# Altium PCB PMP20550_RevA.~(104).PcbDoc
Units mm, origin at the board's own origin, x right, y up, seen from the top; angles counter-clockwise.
Board outline 49.95 x 50.01 mm, 4 copper layers (Top Layer, POWER, GNDS, Bottom Layer), stack 2.028 mm thick; 55 components, 23 nets, 128 pads, 85 vias.
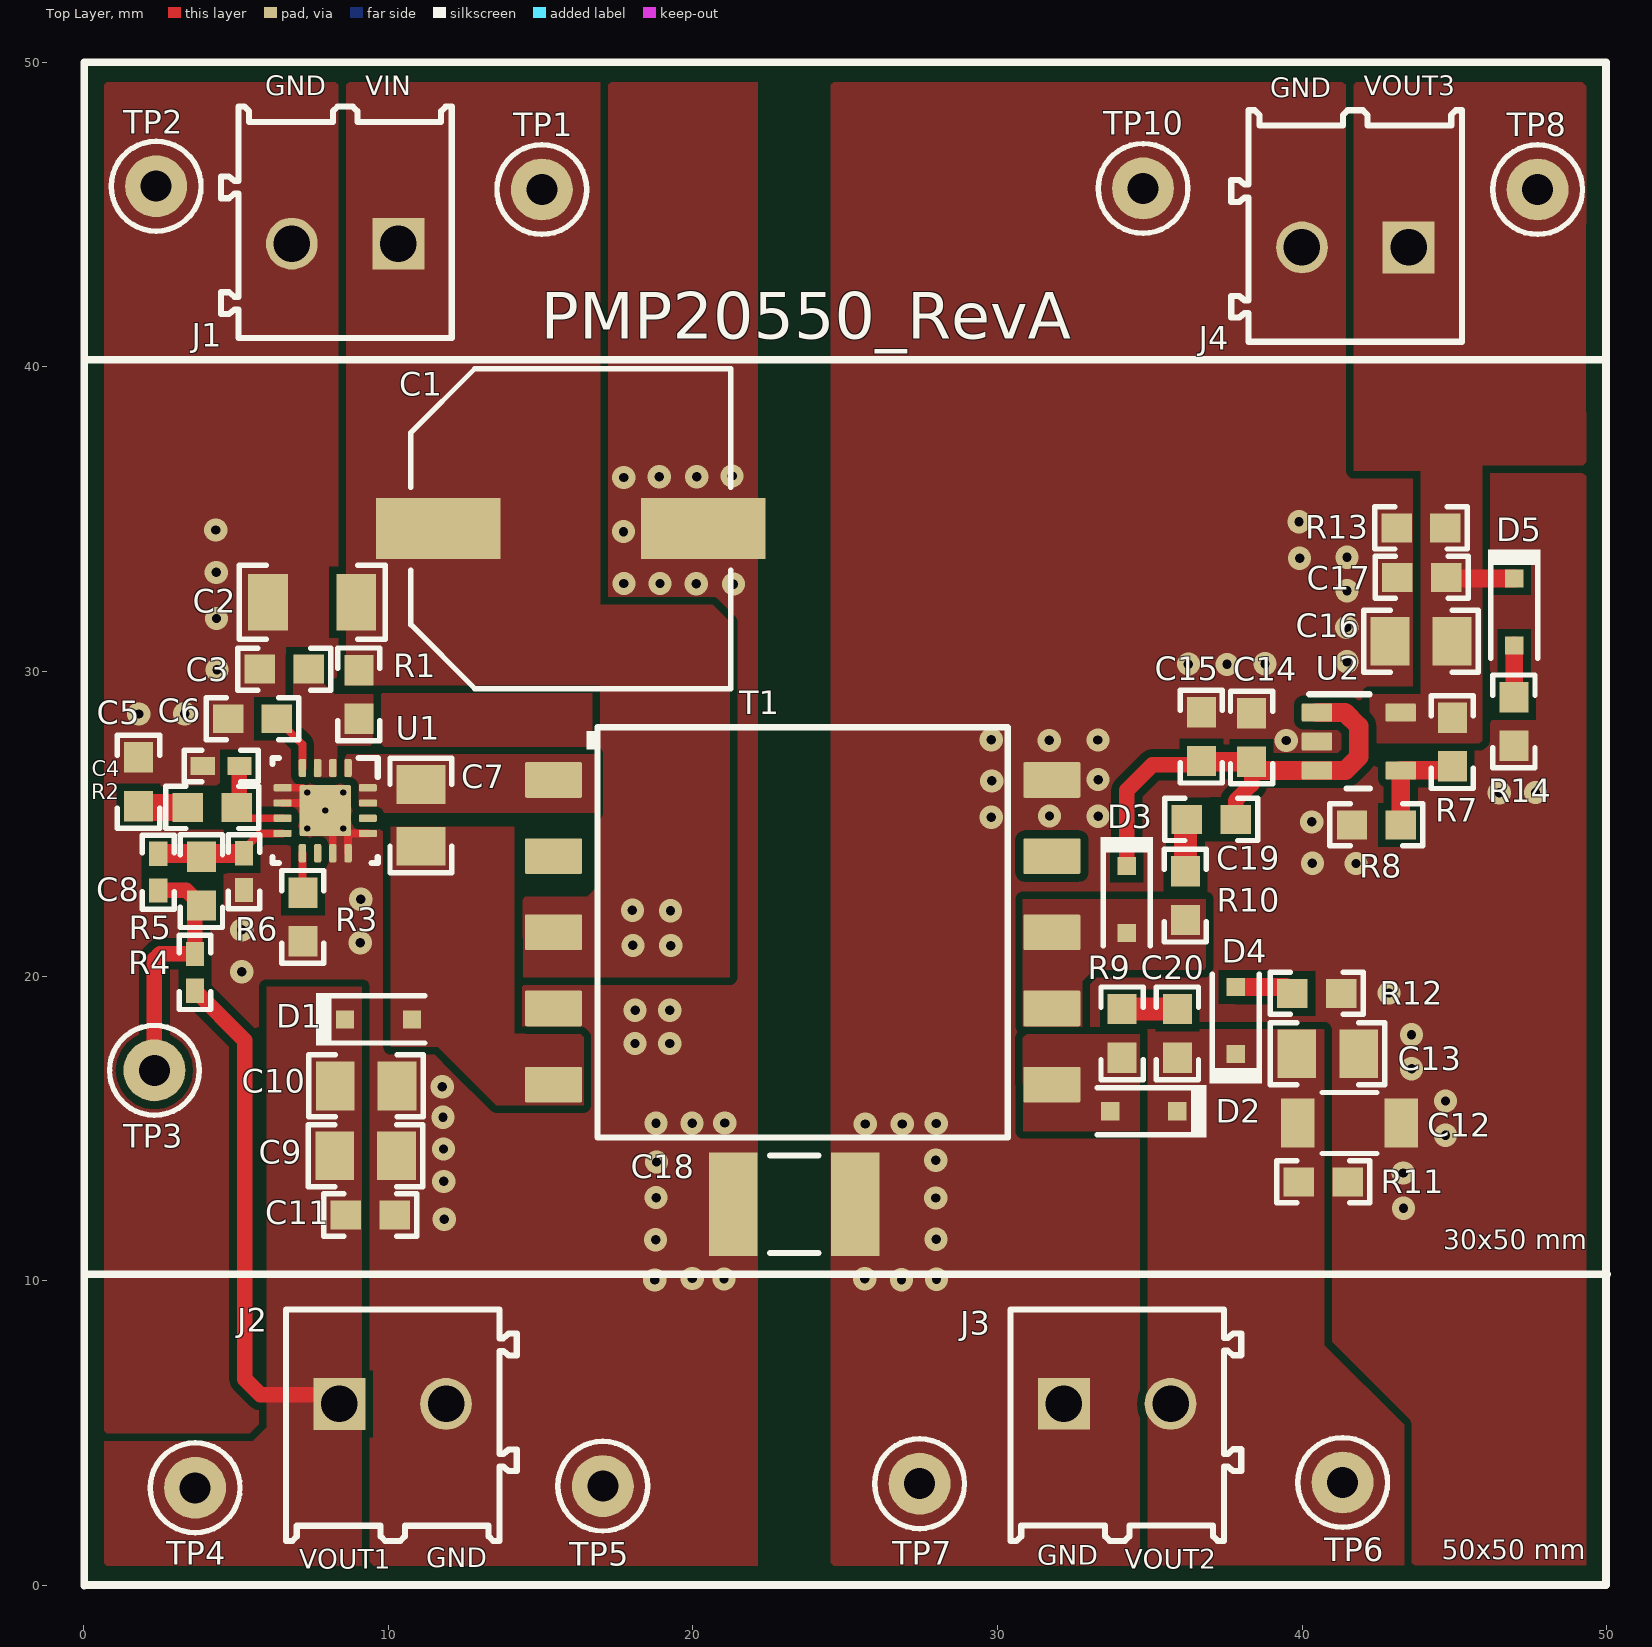
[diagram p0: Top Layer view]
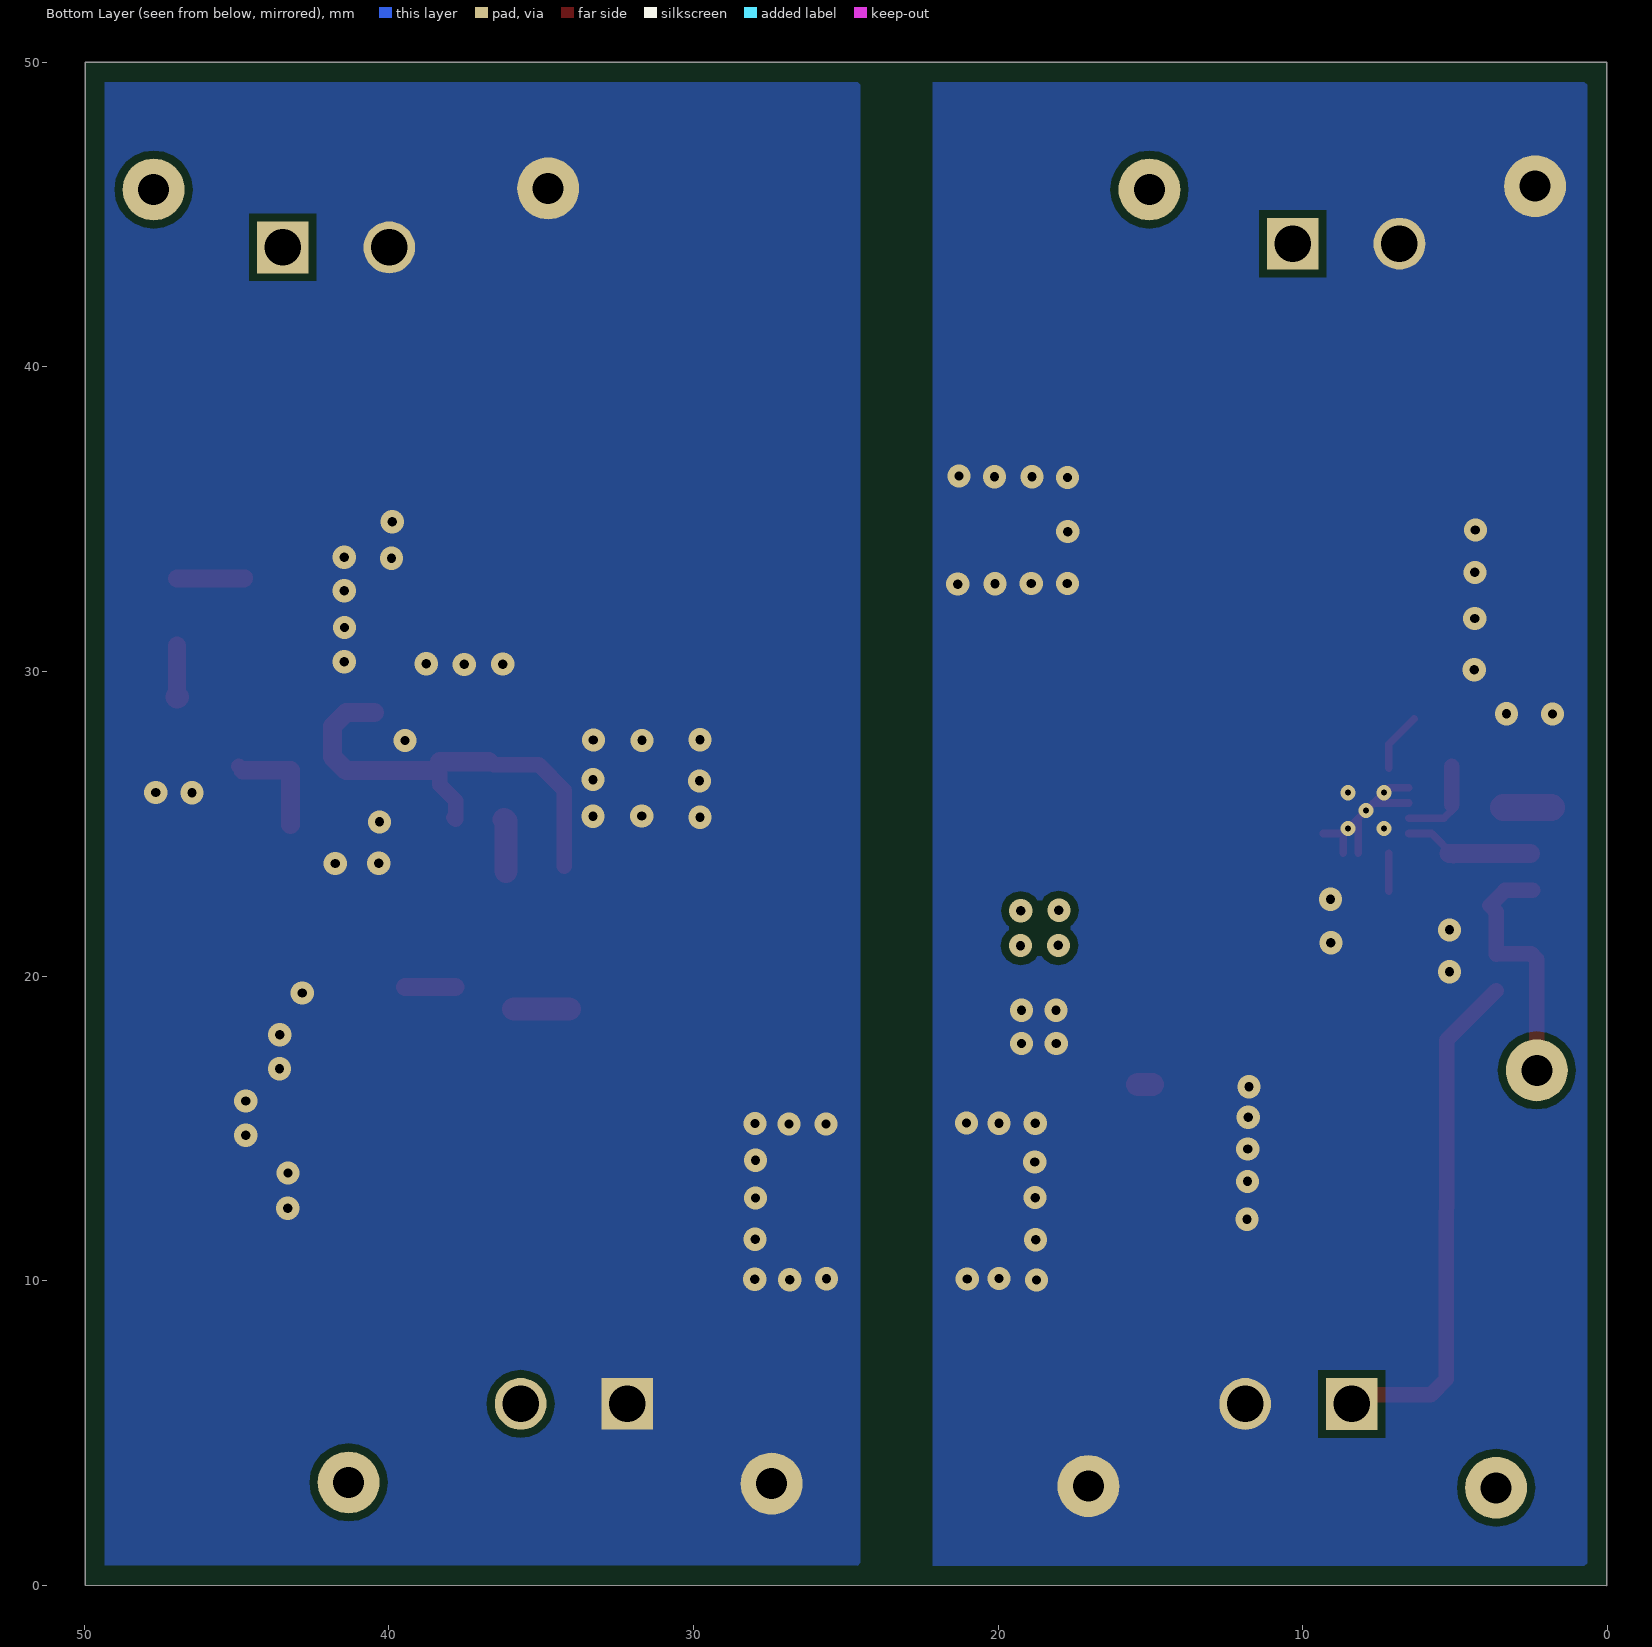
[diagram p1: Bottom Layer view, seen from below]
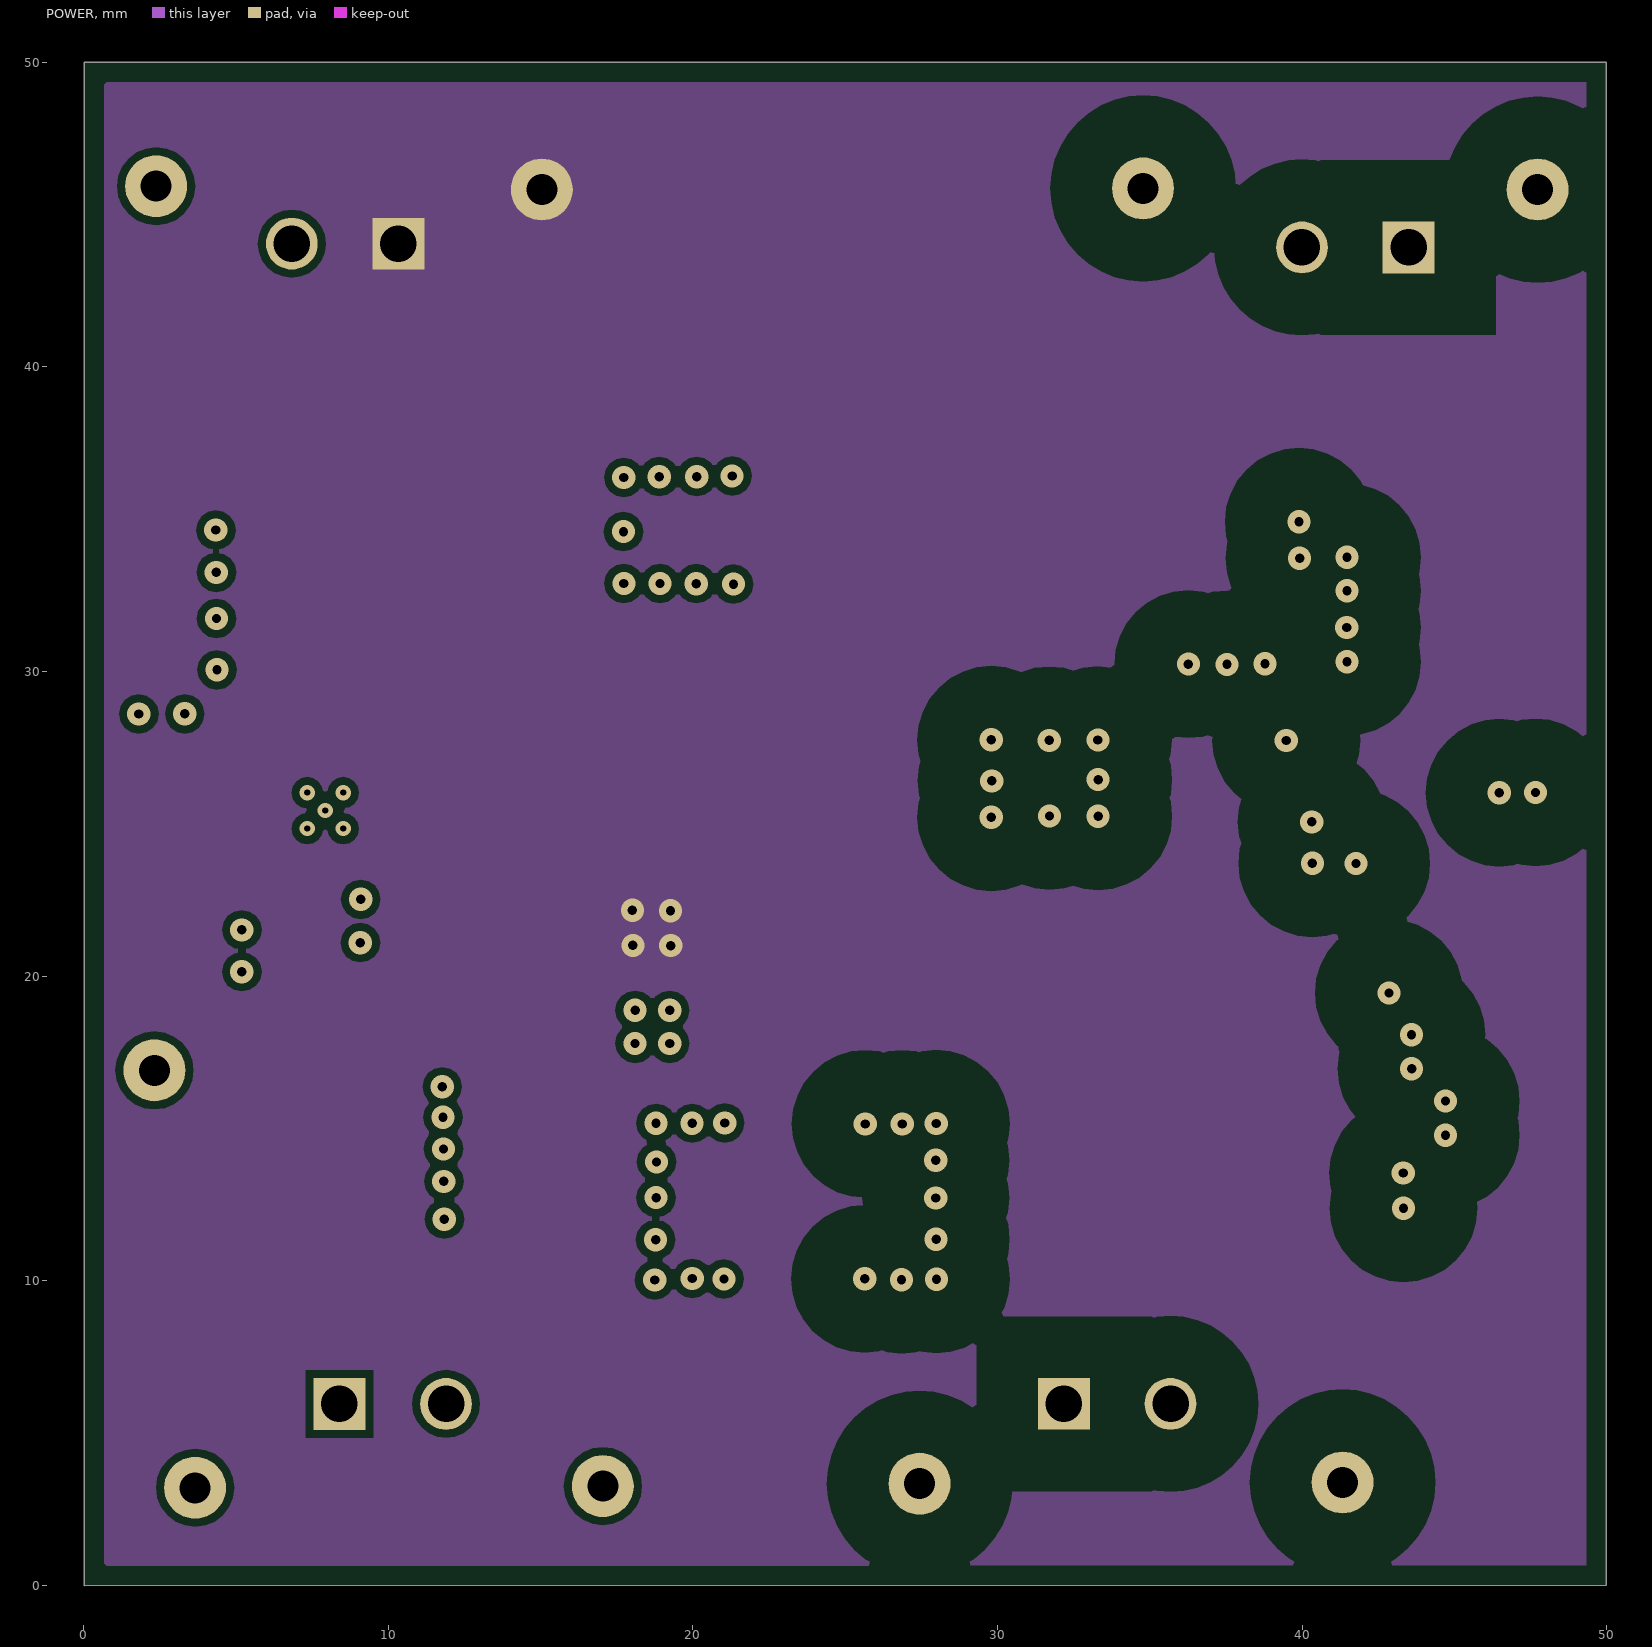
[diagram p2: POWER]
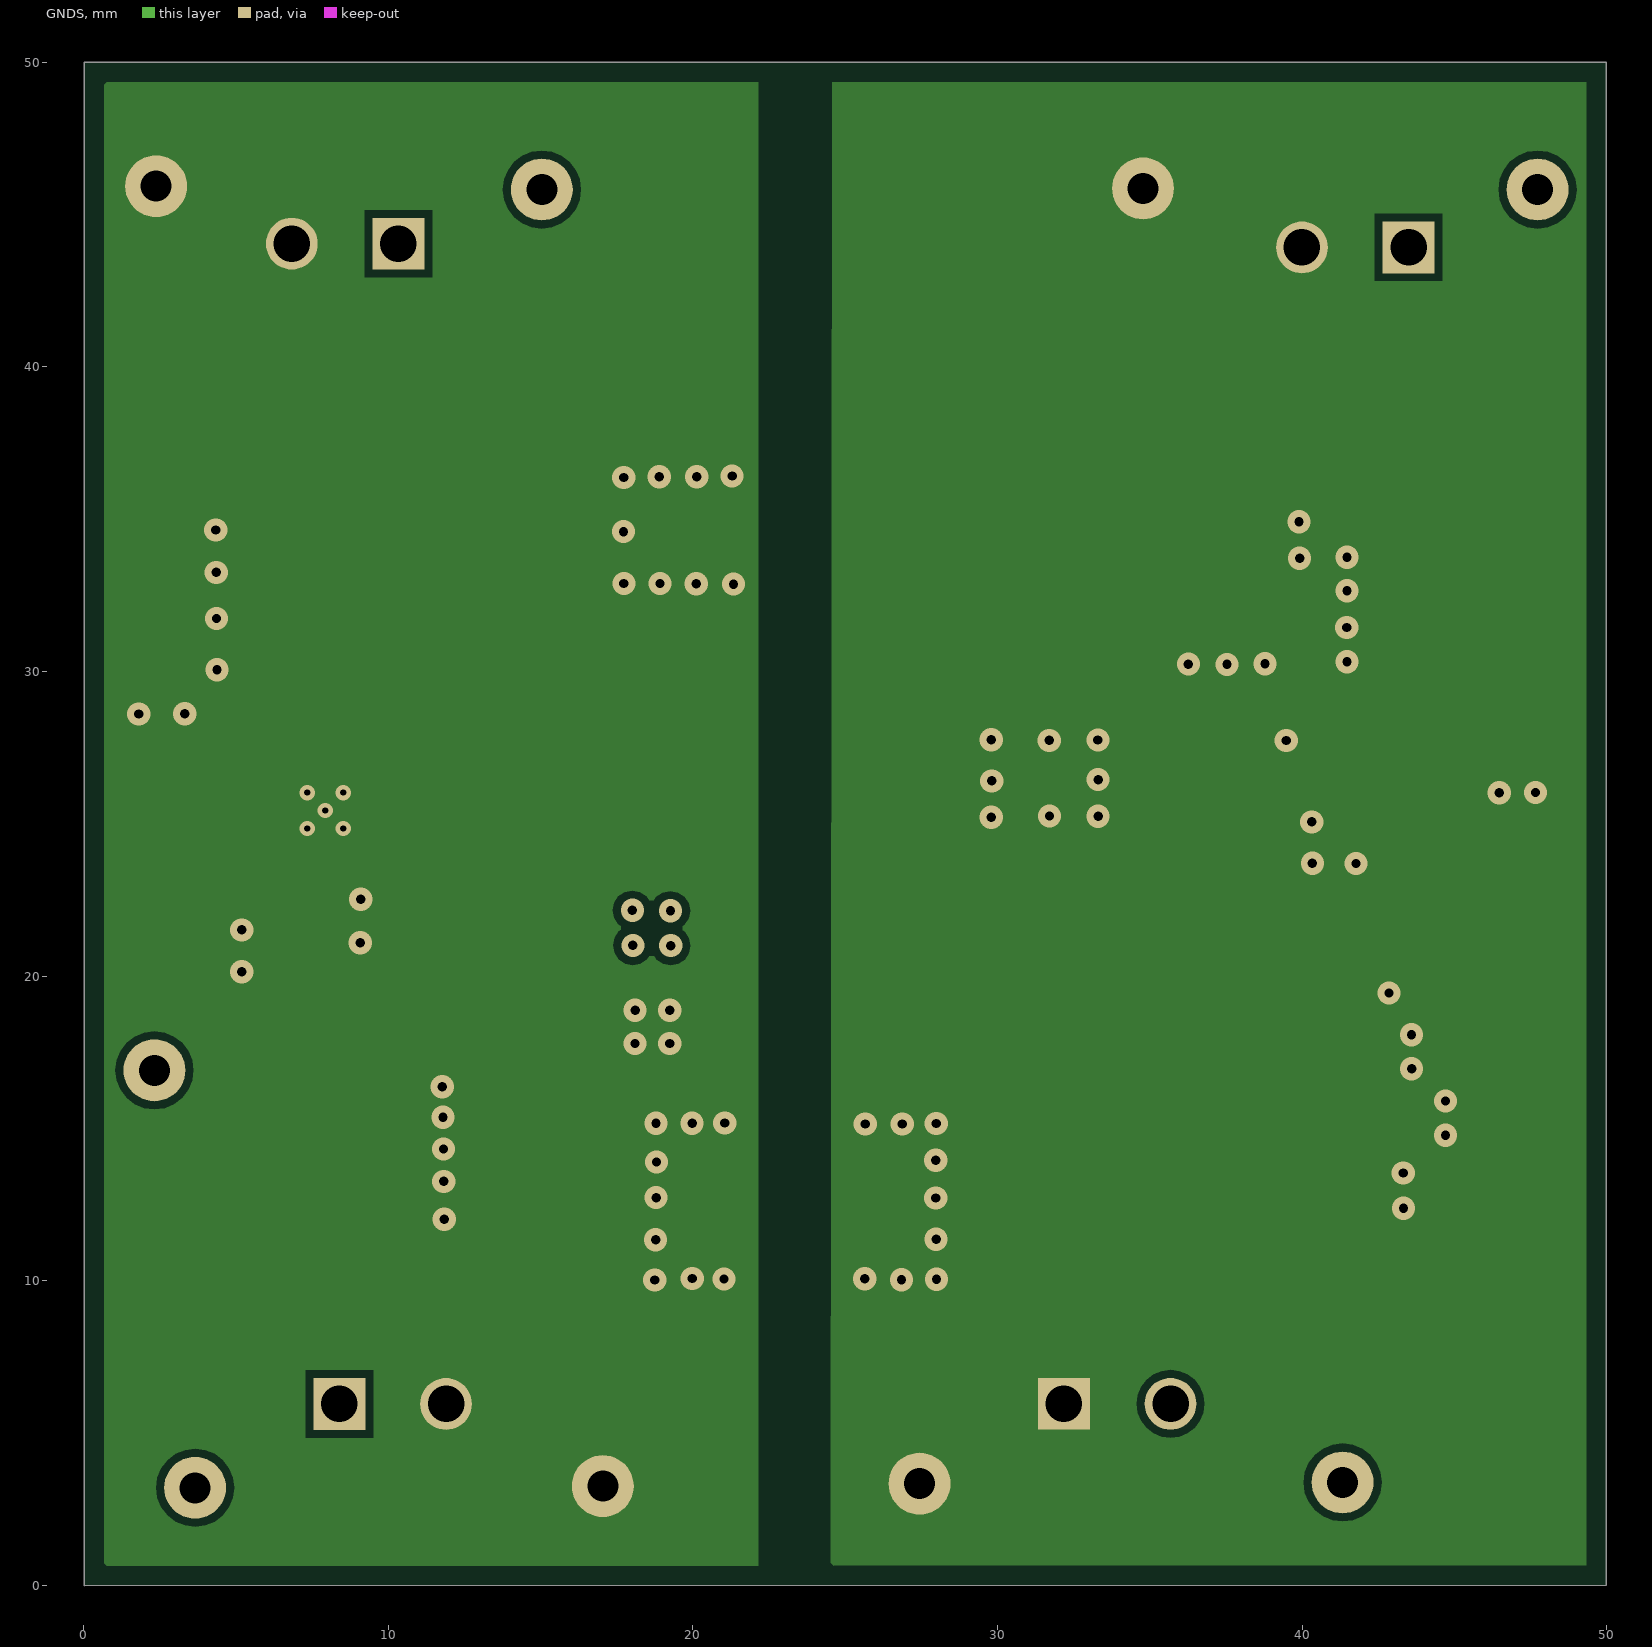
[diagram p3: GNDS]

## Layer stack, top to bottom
Top Solder: solder mask 0.0102, Solder Resist, Dk 3.5
Top Layer: signal copper 0.0356
Dielectric1: core 1.5037, FR-4, Dk 4.8
POWER: signal copper 0.036
Dielectric 3: prepreg 0.127, Dk 4.2
GNDS: signal copper 0.036
Dielectric 2: core 0.254, Dk 4.2
Bottom Layer: signal copper 0.0356
Bottom Solder: solder mask 0.0102, Solder Resist, Dk 3.5

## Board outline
0.019,-0.011 0.019,49.996 0.021,49.994 49.97,49.994 49.972,49.992 49.972,0.008 49.971,0.01

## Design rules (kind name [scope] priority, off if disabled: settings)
AcuteAngle [All] p1: minimum=4.50000000000000E+0001 checktracksonly=FALSE
AssemblyTestPointUsage [All] p1: valid=2
BoardOutlineClearance BoardOutlineClearance_MountingHoles [OnCopper and InComponentClass('Mounting Holes')] p1: gap=1.016
BoardOutlineClearance BoardOutlineClearance_Poly [OnCopper and IsPoly] p2: gap=0.635
BoardOutlineClearance [OnCopper and Not InComponentClass('Logo') and not InComponentClass('FiducialMark') and not InRegion(1000,500,4000,800) and not InPoly] p3: gap=1.016
Clearance Clearance_2 [InNet('NetC1_1') vs InNetClass('Undefined')] p1: gap=2.032
Clearance Clearance_1 [InNet('GND') vs InNet('GND2')] p2: gap=2.032
Clearance Clearance_Keepouts [((IsTrack Or IsArc) And Not InPoly) And IsFree and IsKeepOut vs ((IsTrack Or IsArc) And Not InPoly) And IsFree and IsKeepOut] p3: gap=0
Clearance Clearance_Poly [InPolygon] p4: gap=0.254
Clearance [All] p5: gap=0.127
ComponentClearance ComponentClearance_MountingHoles_FiducialMarks [InComponentClass('Mounting Holes') vs InComponentClass('FiducialMark')] p1: gap=1.27 collisioncheckmode=3 verticalgap=0.254 showdistances=FALSE
ComponentClearance ComponentClearance_Shunt [InComponentClass('Header') vs InComponentClass('Shunt')] p2: gap=0 collisioncheckmode=3 verticalgap=0 showdistances=FALSE
ComponentClearance ComponentClearance_Logo [InComponentClass('Logo')] p3: gap=1.27 collisioncheckmode=3 verticalgap=0.254 showdistances=FALSE
ComponentClearance ComponentClearance_ScrewToNut [(HasFootprint('NY PMS 440 0025 PH')) vs (HasFootprint('Keystone_1902C'))] p4: gap=0.127 collisioncheckmode=3 verticalgap=0.254 showdistances=FALSE
ComponentClearance ComponentClearance_MountingHoles [InComponentClass('Mounting Holes')] p5: gap=6.35 collisioncheckmode=3 verticalgap=2540 showdistances=FALSE
ComponentClearance ComponentClearance_SmallPassives [HasFootprint('0201*') or HasFootprint('0402*') or HasFootprint('0508') or HasFootprint('0603*') or HasFootprint('0612') or HasFootprint('0805*') or HasFootprint('0815*') or HasFootprint('0830*') or HasFootprint('1206*') or HasFootprint('1210*') or HasFootprint('1808*') or HasFootprint('1812*') or HasFootprint('1825*') or HasFootprint('2010*') or HasFootprint('2220*') or HasFootprint('2225*') or HasFootprint('2512*') or HasFootprint('2728*') or HasFootprint('3518*') vs HasFootprint('0201*') or HasFootprint('0402*') or HasFootprint('0508') or HasFootprint('0603*') or HasFootprint('0612') or HasFootprint('0805*') or HasFootprint('0815*') or HasFootprint('0830*') or HasFootprint('1206*') or HasFootprint('1210*') or HasFootprint('1808*') or HasFootprint('1812*') or HasFootprint('1825*') or HasFootprint('2010*') or HasFootprint('2220*') or HasFootprint('2225*') or HasFootprint('2512*') or HasFootprint('2728*') or HasFootprint('3518*')] p6: gap=0.38 collisioncheckmode=3 verticalgap=0.254 showdistances=FALSE
ComponentClearance ComponentClearance_THtoSMT [IsThruComponent vs IsSMTComponent] p7: gap=1.016 collisioncheckmode=3 verticalgap=0.762 showdistances=FALSE
ComponentClearance ComponentClearance_THtoTH [IsThruComponent vs IsThruComponent] p8: gap=0.762 collisioncheckmode=3 verticalgap=0.762 showdistances=FALSE
ComponentClearance [All] p9: gap=0.762 collisioncheckmode=3 verticalgap=0.254 showdistances=FALSE
DiffPairsRouting [All] p1: maxlimit=2.54 minlimit=0.254 mostfreqgap=0.254 toplayer_minwidth=0.381 toplayer_maxwidth=0.381 toplayer_prefwidth=0.381 midlayer1_minwidth=0.381 midlayer1_maxwidth=0.381 midlayer1_prefwidth=0.381 midlayer2_minwidth=0.381 midlayer2_maxwidth=0.381 midlayer2_prefwidth=0.381 bottomlayer_minwidth=0.381 bottomlayer_maxwidth=0.381 bottomlayer_prefwidth=0.381 maxuncoupledlength=25.4
FabricationTestPointUsage TestPointUsage [All] p1: valid=2 allowmultiple=FALSE
FabricationTestpoint Testpoint [All] p1: side=3 testpointundercomponent=TRUE minsize=1.016 maxsize=2.54 preferedsize=1.524 minholesize=0 maxholesize=1.016 preferedholesize=0.813 testpointgrid=0.025 allowsidetop=TRUE allowsidebottom=TRUE usegrid=TRUE gridtolerance=0
FanoutControl Fanout_LCC [IsLCC] p1: bgadir=Out bgaviamode=Centered fanoutstyle=Auto fanoutdirection=Alternating viagrid=0.025 // Fanout_LCC (Default Rule)
FanoutControl Fanout_BGA [IsBGA] p2: bgadir=Out bgaviamode=Centered fanoutstyle=Auto fanoutdirection=Alternating viagrid=0.025 // Fanout_BGA (Default Rule)
FanoutControl Fanout_Default [All] p4: bgadir=Out bgaviamode=Centered fanoutstyle=Auto fanoutdirection=Alternating viagrid=0.025 // Fanout_Default (Default Rule)
FanoutControl Fanout_Small [(CompPinCount < 5)] p5: bgadir=Out bgaviamode=Centered fanoutstyle=Auto fanoutdirection=OutThenIn viagrid=0.025 // Fanout_Small (Default Rule)
HoleSize [All] p1: absolutevalues=TRUE maxlimit=6.375 minlimit=0.2 maxpercent=80.000 minpercent=20.000
MinimumAnnularRing MinimumAnnularRing_ThermalPadVias [IsVia and InAnyComponent] p1: minimumring=0.15
MinimumAnnularRing [All] p2: minimumring=0.203
MinimumSolderMaskSliver MinimumSolderMaskSliver_Logo [InComponentClass('Logo') vs InComponentClass('Logo')] p1: minsoldermaskwidth=0.018
MinimumSolderMaskSliver [All] p2: minsoldermaskwidth=0.1
PlaneConnect [All] p1: planeconnectstyle=Direct reliefexpansion=0.254 reliefentries=4 reliefconductorwidth=0.254 reliefairgap=0.254
PolygonConnect [All] p1: connectstyle=Direct reliefconductorwidth=0.254 reliefentries=4 polygonreliefangle="90 Angle" airgapwidth=0.254
RoutingVias ThermalPadVias [IsVia and InAnyComponent] p1: holewidth=0.2 width=0.5 viastyle="Through Hole" minholewidth=0.2 minwidth=0.5 maxholewidth=0.33 maxwidth=0.6
RoutingVias [All] p2: holewidth=0.406 width=0.864 viastyle="Through Hole" minholewidth=0.2 minwidth=0.66 maxholewidth=1.016 maxwidth=1.651
SilkToBoardRegionClearance [Not ((IsComment or IsDesignator) And (Hide <> 'False')) and not InRegion(1000,500,4000,800)] p1:
SilkToSilkClearance SilkToSilkClearance_Pb-FreeLogo [(HasFootprint('Pb-Free_Overlay_Medium') OR HasFootprint('Pb-Free_Overlay_Small')) vs (HasFootprint('Pb-Free_Overlay_Medium') OR HasFootprint('Pb-Free_Overlay_Small'))] p1: silktosilkclearance=0
SilkToSilkClearance [All] p2: silktosilkclearance=0
SilkToSolderMaskClearance SilkToComponentPadClearance [IsPad and InAnycomponent] p1: minsilkscreentomaskgap=0.102 clearancetoexposedcopper=TRUE
SilkToSolderMaskClearance "Silk to Solder Mask Opening" [All] p2: minsilkscreentomaskgap=0 clearancetoexposedcopper=FALSE
SolderMaskExpansion [All] p1: expansion=0.05
Width [All] p1: maxlimit=2.54 minlimit=0.152 preferedwidth=0.254 checkconnectedcopper=TRUE
15 further rules are at their usual default settings.

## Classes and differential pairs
net class Undefined: GND2 NetC12_1 NetC14_1 NetC16_1 NetC19_2 NetC20_2 NetD2_2 NetD3_2 NetD4_2 NetD5_2 NetR7_1

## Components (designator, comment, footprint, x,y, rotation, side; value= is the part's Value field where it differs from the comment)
C1 "EEE-FC1V221P" SM_RADIAL_G 15.986,34.687 r0 top
C2 "GMK316AB7106KL" 1206 7.5,32.273 r180 top
C3 "C1608X7R1E104K080AA" 0603 6.581,30.076 r180 top
C4 "GRM155R71E333KA88D" 0402 4.512,26.896 r180 top
C5 "C1608X7R1E104K080AA" 0603 1.799,26.381 r90 top
C6 "C1608X7R1E104K080AA" 0603 5.541,28.447 r180 top
C7 "LMK212B7105KG-T" 0805_HV 11.07,25.276 r90 top
C8 "GRM1555C1H201JA01D" 0402 2.446,23.41 r90 top
C9 "GRM21BZ71A226ME15L" 0805_HV 9.251,14.098 r0 top
C10 "GRM21BZ71A226ME15L" 0805_HV 9.269,16.395 r0 top
C11 "C0603X104K8RACTU" 0603 9.407,12.156 r0 top
C12 "C3216X5R1E336M160AC" 1206_180 41.549,15.179 r0 top
C13 "08053C104KAT2A" 0805_HV 40.835,17.451 r0 top
C14 "GRM188Z71A106MA73D" 0603 38.337,27.833 r90 top
C15 "C1608X7R1E104K080AA" 0603 36.686,27.861 r90 top
C16 "C2012X7R1E474K125AA" 0805_HV 43.899,30.995 r180 top
C17 "C0603X104K8RACTU" 0603 43.922,33.09 r180 top
C18 "GR443QR73D102KW01L" 1812 23.323,12.504 r180 top
C19 "GRM1885C1H111JA01D" 0603 37.014,25.143 r180 top
C20 "GRM1885C1H111JA01D" 0603 35.902,18.119 r90 top
D1 "PMEG2020EJ,115" SOD-323F 9.675,18.577 r0 top
D2 "PMEG2020EJ,115" SOD-323F 34.796,15.56 r180 top
D3 "PMEG2020EJ,115" SOD-323F 34.24,22.512 r270 top
D4 "MMSZ5235BS-7-F" SOD-323 37.815,18.539 r90 top
D5 "MMSZ5235BS-7-F" SOD-323 46.957,31.95 r270 top
J1 "1984617" Phoenix_1984617 8.58,44.042 r180 top
J2 "1984617" Phoenix_1984617 10.143,5.956 r0 top
J3 "1984617" Phoenix_1984617 33.926,5.959 r0 top
J4 "1984617" Phoenix_1984617 41.74,43.922 r180 top
R1 "ERJ-3GEY0R00V" 0603 9.033,29.247 r90 top
R2 "RC0603FR-073K01L" 0603 4.216,25.535 r0 top
R3 "CRCW0603162KFKEA" 0603 7.194,21.943 r90 top
R4 "ERJ-2RKF49R9X" 0402 3.651,20.123 r270 top
R5 "CRCW060330K9FKEA" 0603 3.863,23.117 r270 top
R6 "ERJ-2RKF1002X" 0402 5.258,23.427 r90 top
R7 "RC0603FR-0778K7L" 0603 44.928,27.681 r90 top
R8 "CRCW060324K9FKEA" 0603 42.433,24.964 r0 top
R9 "CPF0603B1K62E" 0603 34.084,18.119 r270 top
R10 "CPF0603B1K62E" 0603 36.163,22.641 r270 top
R11 "CPF0603B1K62E" 0603 40.689,13.247 r0 top
R12 "CPF0603B1K62E" 0603 40.478,19.432 r0 top
R13 "CPF0603B1K62E" 0603 43.899,34.712 r180 top
R14 "CPF0603B1K62E" 0603 46.947,28.36 r270 top
T1 "750316553" Wurth_750316553 23.602,21.438 r0 top
TP1 "5000" Keystone5000 15.038,45.82 r90 top
TP2 "5001" Keystone5001 2.377,45.929 r90 top
TP3 "5003" Keystone5003 2.32,16.906 r0 top
TP4 "VBUS" Keystone5000 3.656,3.203 r90 top
TP5 "5001" Keystone5001 17.039,3.257 r90 top
TP6 "5000" Keystone5000 41.326,3.378 r0 top
TP7 "5001" Keystone5001 27.438,3.338 r0 top
TP8 "5000" Keystone5000 47.725,45.82 r0 top
TP10 "5001" Keystone5001 34.774,45.857 r90 top
U1 "TPS55340QRTERQ1" RTE0016C 7.928,25.432 r270 top
U2 "TPS73201QDBVRQ1" DBV0005A_N 41.855,27.701 r0 top

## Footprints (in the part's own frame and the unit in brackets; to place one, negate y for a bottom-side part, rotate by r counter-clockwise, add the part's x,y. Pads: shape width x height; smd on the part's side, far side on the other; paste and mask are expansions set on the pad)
0402 [mm] "0402 from SM-752 data"
  rect 0.8x0.6 smd: 1(-0.6,0) 2(0.6,0)
  silkscreen extent -1.22,-0.52 1.22,0.52, body extent -0.55,-0.3 0.55,0.3, height 0.6
0603 [mm] "0603 from SM-752 data"
  rect 1x0.95 smd: 1(-0.8,0) 2(0.8,0)
  silkscreen extent -1.52,-0.69 1.52,0.69, body extent -0.87,-0.47 0.87,0.47, height 1
0805_HV [mil] "0805 with 30mil clearance between pads"
  rect 50x63 smd: 1(-40,0) 2(40,0)
  silkscreen extent -74,-40 74,40, body extent -43,-29 43,29, height 57
1206 [mm] "1206 from SM-752 data"
  rect 1.3x1.85 smd: 1(-1.45,0) 2(1.45,0)
  silkscreen extent -2.4,-1.21 2.4,1.21, body extent -1.7,-0.9 1.7,0.9, height 1.35
1206_180 [mm] "1206_180"
  rect 1.1x1.6 smd: 1(-1.7,0) 2(1.7,0)
  silkscreen extent -0.9,-1 0.9,1, body extent -1.75,-0.95 1.75,0.95, height 1.8
1812 [mm]
  rect 1.6x3.4 smd: 1(-2,0) 2(2,0)
  silkscreen extent -0.8,-1.6 0.8,1.6, body extent -2.4,-1.7 2.4,1.7, height 1.35
DBV0005A_N [mm] "SOT23, 5-Leads, Body 2.9x1.6mm, Pitch 0.95mm, Lead Span 2.8mm, IPC Medium Density"
  rrect17% 1x0.6 smd: 1(-1.375,0.95) 2(-1.375,0) 3(-1.375,-0.95) 4(1.375,-0.95) 5(1.375,0.95)
  silkscreen extent -1.63,-1.55 0.38,1.55, body extent -1.42,-1.46 1.42,1.46, height 1.09
Keystone5000 [mil] "For Keystone 500x miniature loop terminals"
  round 80 hole 40: 1(0,0)
  silkscreen extent -58,-58 58,58, body extent -49,-49 49,49, height 182
Keystone5001 [mil] "For Keystone 500x miniature loop terminals"
  round 80 hole 40: 1(0,0)
  silkscreen extent -58,-58 58,58, body extent -49,-49 49,49, height 182
Keystone5003 [mil] "For Keystone 500x miniature loop terminals"
  round 80 hole 40: 1(0,0)
  silkscreen extent -58,-58 58,58, body extent -49,-49 49,49, height 182
Phoenix_1984617 [mm] "Terminal Block, 3.5mm, 2x1, TH"
  rect 1.7x1.7 hole 1.2: 1(-1.75,0)
  round 1.7 hole 1.2: 2(1.75,0)
  silkscreen extent -3.5,-4.5 4.07,3.1, body extent -3.5,-4.5 4.07,3.1, height 9
RTE0016C [mm] "Texas Insturments"
  rrect42% 0.6x0.24 smd: 1(-1.4,0.75) 2(-1.4,0.25) 3(-1.4,-0.25) 4(-1.4,-0.75) 9(1.4,-0.75) 10(1.4,-0.25) 11(1.4,0.25) 12(1.4,0.75)
  rrect42% 0.24x0.6 smd: 5(-0.75,-1.4) 6(-0.25,-1.4) 7(0.25,-1.4) 8(0.75,-1.4) 13(0.75,1.4) 14(0.25,1.4) 15(-0.25,1.4) 16(-0.75,1.4)
  rrect6% 1.55x1.55 on Top Paste: 17(0,0)
  rrect6% 1.68x1.68 smd paste-0.85: 17(0,0)
  silkscreen extent -1.72,-1.73 1.72,1.73, body extent -1.57,-1.57 1.58,1.58, height 0.81
SM_RADIAL_G [mm] "10 x 10.2mm:  Panasonic G"
  rect 4.1x2 smd: 1(-4.35,0) 2(4.35,0)
  silkscreen extent -5.25,-5.25 5.25,5.25, body extent -5.25,-5.25 5.25,5.25, height 10.5
SOD-323 [mm] "NXP recommended land pattern"
  rect 0.6x0.6 smd paste-0.05: 1(-1.1,0) 2(1.1,0)
  silkscreen extent -2.06,-0.86 1.53,0.86, body extent -1.3,-0.67 1.3,0.68, height 1.1
SOD-323F [mm] "NXP recommended land pattern"
  rect 0.6x0.6 smd paste-0.05: 1(-1.1,0) 2(1.1,0)
  silkscreen extent -2.06,-0.86 1.53,0.86, body extent -1.35,-0.67 1.35,0.68, height 0.79
Wurth_750316553 [mm] "SMD, 10-Leads, Body 17.75x13.46mm, Pitch 2.5mm"
  rrect9% 1.88x1.17 smd: 1(-8.18,5) 2(-8.18,2.5) 3(-8.18,0) 4(-8.18,-2.5) 5(-8.18,-5) 6(8.18,-5) 7(8.18,-2.5) 8(8.18,0) 9(8.18,2.5) 10(8.18,5)
  silkscreen extent -7.1,-6.73 6.73,6.73, body extent -8.87,-6.73 8.88,6.73, height 12.7

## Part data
C1: "CAP, AL, 220 µF, 35 V, +/- 20%, 0.15 ohm, SMD"
C2: "CAP, CERM, 10 µF, 35 V, +/- 10%, X7R, 1206"
C3 C5 C6 C15: "CAP, CERM, 0.1 µF, 25 V, +/- 10%, X7R, 0603"
C4: "OPEN, 0402"
C7: "CAP, CERM, 1 µF, 10 V, +/- 10%, X7R, 0805"
C8: "CAP, CERM, 200 pF, 50 V, +/- 5%, C0G/NP0, 0402"
C9 C10: "CAP, CERM, 22 µF, 10 V, +/- 20%, X7R, 0805"
C11 C17: "CAP, CERM, 0.1 µF, 10 V, +/- 10%, X7R, 0603"
C12: "CAP, CERM, 33 µF, 25 V, +/- 20%, X5R, 1206"
C13: "CAP, CERM, 0.1 µF, 25 V, +/- 10%, X7R, 0805"
C14: "CAP, CERM, 10 µF, 10 V, +/- 20%, X7R, 0603"
C16: "CAP, CERM, 4.7 µF, 25 V, +/- 10%, X7R, 0805"
C18: "CAP, CERM, 1000 pF, 2000 V, +/- 10%, X7R, 1812"
C19 C20: "CAP, CERM, 110 pF, 50 V, +/- 5%, C0G/NP0, 0603"
D1 D2 D3: "Diode, Schottky, 20 V, 2 A, SOD-323F"
D4 D5: "Diode, Zener, 6.8 V, 200 mW, SOD-323"
J1 J2 J3 J4: "Terminal Block, 3.5mm, 2x1, TH"
R1: "RES, 0, 5%, 0.1 W, 0603"
R2: "RES, 3.01 k, 1%, 0.1 W, 0603"
R3: "RES, 162 k, 1%, 0.1 W, 0603"
R4: "RES, 49.9, 1%, 0.1 W, AEC-Q200 Grade 0, 0402"
R5: "RES, 30.9 k, 1%, 0.1 W, 0603"
R6: "RES, 10.0 k, 1%, 0.1 W, 0402"
R7: "RES, 78.7 k, 1%, 0.1 W, 0603"
R8: "RES, 24.9 k, 1%, 0.1 W, 0603"
R9 R10 R11 R12 R13 R14: "RES, 1.62 k, 0.1%, 0.063 W, 0603"
T1: "Transformer, 52 uH, SMT"
TP1 TP6 TP8: "Test Point, Miniature, Red, TH"
TP2 TP5 TP7 TP10: "Test Point, Miniature, Black, TH"
TP3: "Test Point, Miniature, Orange, TH"
TP4: library part 5000, "Test Point, TH, Miniature, Red"
U1: "Integrated 5-A 40-V Wide Input Range Boost/SEPIC/Flyback DC-DC Regulator, RTE0016C"
U2: "Single Output Fast Transient Response LDO, 250 mA, Adjustable 1.2 to 5.5 V Output, 1.7 to 5.5 V Input, 5-pin SOT-23 (DBV), -40 to 125 degC, Green (RoHS & no Sb/Br)"

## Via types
v1: diameter 0.762, hole 0.305, Top Layer to Bottom Layer, tented top, 73 vias
v2: diameter 0.762, hole 0.305, Top Layer to Bottom Layer, 7 vias
v3: diameter 0.5, hole 0.2, Top Layer to Bottom Layer, tented top, 5 vias

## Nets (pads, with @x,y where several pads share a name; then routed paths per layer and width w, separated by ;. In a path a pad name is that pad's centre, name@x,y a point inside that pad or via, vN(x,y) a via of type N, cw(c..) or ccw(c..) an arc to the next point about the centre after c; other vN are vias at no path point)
GND: C1.2 C2.2 C3.2 C4.2 C5.2 C6.2 C9.2 C10.2 C11.2 C18.2 J1.2 J2.2 R3.1 R6.1 T1.4 TP2.1 TP5.1 U1.5 U1.6 U1.11 U1.12 U1.13 U1.17@7.928,25.432 | length 6.1
  Top Layer w0.254: U1.6 U1.17@7.678,25.682 ; U1.5 U1.17@7.178,26.182 ; v3(7.338,26.022) U1.17@7.678,25.682 ; U1.11 U1.17@8.178,25.182 ; U1.12 U1.17@8.678,24.682 ; U1.13 U1.17@8.678,24.682 ; U1.17@7.678,25.682 v3(7.928,25.432) U1.17@8.178,25.182 ; U1.17@8.178,25.182 U1.17@8.678,24.682
  other v1: 18.742,10.023 21.015,10.057 19.976,10.072 18.773,11.348 11.836,12.019 18.789,12.728 11.821,13.261 18.801,13.899 11.808,14.326 18.788,15.168 19.972,15.168 21.042,15.18 11.795,15.365 11.769,16.364 18.099,17.79 19.235,17.79 18.1,18.878 19.235,18.878 5.189,20.142 9.08,21.095 5.189,21.517 9.092,22.519 1.807,28.605 3.316,28.61 4.374,30.054 4.357,31.738 21.328,32.867 17.731,32.888 18.918,32.888 20.105,32.881 4.353,33.252 17.716,34.59 4.336,34.641 17.729,36.368 18.893,36.393 20.12,36.393 21.285,36.418
  other v3: 7.338,24.842 8.518,24.842 8.518,26.022
GND2: C12.2 C13.2 C14.2 C15.2 C16.2 C17.2 C18.1 J3.1 J4.2 R8.1 R11.2 R12.2 R13.2 R14.2 T1.10 TP7.1 TP10.1 U2.2
  other v1: 26.846,10.034 25.636,10.063 27.993,10.046 27.981,11.363 43.323,12.379 27.968,12.717 43.315,13.537 27.969,13.955 44.704,14.774 25.655,15.148 26.869,15.148 27.983,15.16 44.704,15.902 43.59,16.959 43.583,18.073 42.845,19.447 40.333,23.707 41.767,23.697 40.313,25.063 31.705,25.255 33.299,25.247 46.469,26.019 47.659,26.029 33.299,26.449 31.697,27.738 33.291,27.747 39.477,27.732 37.531,30.232 36.262,30.241 38.777,30.251 41.469,30.318 41.462,31.444 41.469,32.649 39.914,33.715 41.469,33.747 39.89,34.913
  other v2: 29.792,25.217 29.809,26.408 29.792,27.758
NetC1_1: C1.1 C2.1 J1.1 R1.2 T1.3 TP1.1
  other v2: 18.026,21.008 19.267,20.999 18.01,22.158 19.258,22.141
NetC3_1: C3.1 R1.1 U1.2 U1.3
NetC4_1: C4.1 R2.2 U1.7 | length 3.1
  Top Layer w0.254: R2.2@5.112,25.632 R2.2 5.369,25.182 U1.7
  Top Layer w0.508: R2.2@5.112,25.632 C4.1
NetC5_1: C5.1 R2.1 | length 1.6
  Top Layer w0.508: C5.1 C5.1@1.845,25.535
  Top Layer w0.889: C5.1@1.845,25.535 R2.1
NetC6_1: C6.1 U1.4 | length 2
  Top Layer w0.254: C6.1 7.178,27.61 U1.4
NetC7_1: C7.1 D1.2 T1.5 | length 0.5
  Top Layer w0.762: T1.5@14.938,16.438 T1.5
NetC7_2: C7.2 T1.1 U1.1 U1.15 U1.16
NetC8_1: C8.1 R4.1 R5.2 TP3.1 | length 8.4
  Top Layer w0.508: TP3.1 2.32,20.55 2.504,20.733 3.641,20.733 R4.1 3.651,22.106 R5.2 3.37,22.81 C8.1
NetC8_2: C8.2 R5.1 R6.2 U1.8 | length 4.6
  Top Layer w0.254: R6.2@5.045,23.953 5.774,24.682 U1.8
  Top Layer w0.508: 4.93,24.068 R6.2@5.045,23.953
  Top Layer w0.635: C8.2@2.53,24.024 R6.2@5.199,24.024
NetC9_1: C9.1 C10.1 C11.1 D1.1 J2.1 R4.2 TP4.1 | length 16.9
  Top Layer w0.508: R4.2 5.281,17.894 5.285,6.77 5.799,6.256 8.093,6.256 J2.1
NetC12_1: C12.1 C13.1 C20.1 D2.1 D4.1 J3.2 R11.1 TP6.1
NetC14_1: C14.1 C15.1 C19.1 D3.1 U2.1 U2.3 | length 15.6
  Top Layer w0.508: D3.1 34.24,26.099 35.079,26.938 36.564,26.938 C15.1 C15.1@36.714,27.033 ; C19.1@37.878,25.206 C19.1 37.814,25.763 38.337,26.286 C14.1 C14.1@38.618,26.751
  Top Layer w0.635: C15.1@36.714,27.033 C14.1 ; C14.1@38.618,26.751 U2.3 41.409,26.751 41.855,27.197 41.855,28.201 41.405,28.651 U2.1
NetC16_1: C16.1 C17.1 D5.1 J4.1 R7.2 R13.1 TP8.1 U2.5 | length 2.3
  Top Layer w0.508: C17.1 C17.1@44.762,33.05
  Top Layer w0.584: C17.1@44.762,33.05 D5.1
NetC19_2: C19.2 R10.1 | length 1.7
  Top Layer w0.762: R10.1 36.163,25.091 C19.2
NetC20_2: C20.2 R9.1 | length 1.8
  Top Layer w0.762: R9.1 C20.2
NetD2_2: D2.2 R9.2 T1.6
NetD3_2: D3.2 R10.2 T1.7 T1.8
NetD4_2: D4.2 R12.1 | length 1.7
  Top Layer w0.584: D4.2 R12.1@39.471,19.639
NetD5_2: D5.2 R14.1 | length 1.7
  Top Layer w0.584: R14.1@46.957,29.17 D5.2
  Top Layer w0.762: R14.1 R14.1@46.957,29.17
NetR3_2: R3.2 U1.9 | length 1.2
  Top Layer w0.254: U1.9 R3.2@7.179,22.782
NetR7_1: R7.1 R8.2 U2.4 | length 3.5
  Top Layer w0.508: R7.1@44.798,26.751 R7.1
  Top Layer w0.61: R8.2 43.233,26.749 U2.4 R7.1@44.798,26.751
pads on no net: T1.2 T1.9 U1.10 U1.14 U1.17@7.928,25.432

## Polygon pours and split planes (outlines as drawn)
NetC3_1 on Top Layer "Top Layer-No Net 4" (solid, pour order 34): 6.891,30.536 6.873,30.518 6.873,27.887 7.535,27.252 7.535,26.496 8.013,26.496 8.321,26.496 8.321,26.811 8.321,27.565 9.502,27.565 9.491,27.981 9.507,27.997 9.507,29.247 8.235,29.247 8.131,29.351 7.864,29.619 7.864,30.545
NetC9_1 on Top Layer "Top Layer-No Net" (solid, pour order 44): 0.667,-0.066 0.667,4.726 5.552,4.726 6.026,5.2 6.002,5.223 6.002,19.642 9.133,19.642 9.133,0.643 10.695,-0.92
NetC7_2 on Top Layer "Top Layer-No Net 3" (solid, pour order 46): 8.389,27.301 8.413,27.277 16.798,27.277 16.798,26.485 16.798,25.368 8.528,25.368
NetC1_1 on Top Layer "Top Layer-No Net 5" (solid, pour order 48): 8.618,49.398 8.618,29.537 8.603,29.522 8.62,29.539 16.96,29.539 16.96,49.355 16.994,49.389
NetC1_1 on Top Layer "Top Layer-No Net 6" (solid, pour order 52): 14.425,19.984 14.447,19.962 21.21,19.962 21.21,31.627 20.704,32.133 20.645,32.193 16.953,32.193 16.953,23.031 16.564,22.642 16.521,22.598 14.403,22.598
NetC16_1 on Top Layer "Top Layer-No Net 1" (solid, pour order 54): 49.325,49.345 49.315,49.355 41.688,49.355 41.688,38.806 41.688,36.586 43.908,36.586 43.888,36.567 43.888,29.259 42.213,29.259 42.213,27.648 45.813,27.648 45.872,27.589 45.912,27.629 45.912,36.743 45.912,36.763 49.325,36.763 49.31,40.161
NetC12_1 on Top Layer "Top Layer-No Net 8" (solid, pour order 58): 34.928,18.248 40.704,18.248 40.728,18.224 40.728,8.051 40.728,7.885 43.343,5.27 43.343,0.279 35.19,0.279 34.928,0.54
NetD3_2 on Top Layer "Top Layer-No Net 2" (solid, pour order 60): 30.831,22.52 36.838,22.52 36.838,20.174 36.823,20.159 36.779,20.203 33.296,20.203 33.148,20.203 32.794,19.849 32.779,19.834 32.779,18.344 30.846,18.344 30.831,18.329
NetD2_2 on Top Layer "Top Layer-No Net 9" (solid, pour order 64): 30.824,18.086 34.738,18.086 34.738,14.903 34.727,14.914 30.835,14.914
NetC7_1 on Top Layer "Top Layer-No Net 7" (solid, pour order 16): 16.406,15.763 13.538,15.763 12.222,17.079 11.628,17.673 10.081,17.673 10.081,18.557 10.081,19.336 10.081,19.754 10.081,19.868 10.081,24.897 14.129,24.897 14.129,18.1 16.406,18.1
GND on Top Layer "Top Layer-No Net 10" (solid, pour order 66): 22.125,0.184 22.125,49.873 0.142,49.873 0.021,49.994 0.019,49.993 0.019,-0.011
GND2 on Top Layer "Top Layer-No Net 11" (solid, pour order 68): 24.53,0.122 24.53,49.75 24.774,49.994 49.97,49.994 49.97,0.01 49.972,0.008
NetC1_1 on POWER "POWER-No Net" (solid, pour order 18): 0.021,49.994 0.023,49.992 49.972,49.992 49.972,0.008 49.971,0.01 0.04,0.01
GND2 on GNDS "GND2" (solid, pour order 28): 24.523,0.005 49.971,0.01 49.971,49.994 49.877,49.901 24.579,49.901
GND on GNDS "GND1" (solid, pour order 20): 22.141,0.166 0.196,0.166 0.04,0.01 0.021,0.029 0.021,49.994 22.141,49.994
GND2 on Bottom Layer "bot - gnd2" (solid, pour order 42): 50.031,49.962 49.911,50.082 24.529,50.082 24.529,0.2 50.091,0.2
GND on Bottom Layer "bot - gnd1" (solid, pour order 36): 0.089,49.962 22.157,49.962 22.157,48.617 22.157,0.14 0.208,0.14 0.029,-0.04

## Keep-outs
Keep-Out Layer:
  text ".Layer_Name" at 14.656,-21.806 h1.52

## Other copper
Top Layer:
  text ".Layer_Name" at 14.656,-21.806 h1.52
Bottom Layer:
  text ".Layer_Name" at 14.656,-21.806 h1.52

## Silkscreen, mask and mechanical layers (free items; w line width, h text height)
Top Overlay:
  lines w0.254: 0.019,-0.011 0.019,49.996 0.021,49.994 49.97,49.994 49.972,49.992 49.972,0.008 49.971,0.01 0.04,0.01 ; 0.035,10.211 50.001,10.211 ; 0.055,40.233 49.927,40.233
  text "GND" at 5.964,48.919 h0.64
  text "VIN" at 9.245,48.921 h0.64
  text "VOUT3" at 42.025,48.92 h0.64
  text "GND" at 38.956,48.857 h0.64
  text "PMP20550_RevA" at 15.01,40.923 h1.52
  text "30x50 mm" at 44.623,11.025 h0.64
  text "50x50 mm" at 44.579,0.857 h0.64
  text "GND" at 31.3,0.676 h0.64
  text "GND" at 11.251,0.595 h0.64
  text "VOUT1" at 7.071,0.55 h0.64
  text "VOUT2" at 34.168,0.553 h0.64
  text ".Layer_Name" at 14.656,-21.806 h1.52
Bottom Overlay:
  text ".Layer_Name" at 14.656,-21.806 h1.52
Top Paste:
  text ".Layer_Name" at 14.656,-21.806 h1.52
Bottom Paste:
  text ".Layer_Name" at 14.656,-21.806 h1.52
Top Solder:
  text ".Layer_Name" at 14.656,-21.806 h1.52
  text ".Layer_Name" at 14.656,-21.806 h1.52
Bottom Solder:
  text ".Layer_Name" at 14.656,-21.806 h1.52
Drill Guide:
  text ".Layer_Name" at 14.656,-21.806 h1.52
M1 Board Outline:
  text ".Layer_Name" at 14.656,-21.806 h1.52
M2 Board Dimensions:
  rectangle: 0,-6.985 3.175,-3.81
  rectangle: 3.175,-10.16 12.7,-6.985
  lines w0.178: 0,-6.985 25.4,-6.985 ; 3.175,-10.16 3.175,-3.81 ; 6.35,-10.16 6.35,-3.81 ; 12.7,-10.16 12.7,-3.81 ; 19.05,-10.16 19.05,-3.81 ; 0,-10.16 25.4,-10.16 25.4,-3.81 0,-3.81 0,-10.16
  text ".Layer_Name" at 14.656,-21.806 h1.52
M3 3D STEP Top:
  text ".Layer_Name" at 14.656,-21.806 h1.52
M4 3D STEP Bottom:
  text ".Layer_Name" at 14.656,-21.806 h1.52
M5 Assembly Top:
  lines w0.254: -7.417,-23.626 160.223,-23.626 ; -7.417,-18.462 160.274,-18.462 ; -7.417,-13.297 -7.417,-28.791 94.31,-28.791 160.274,-28.791 160.274,-13.297 -7.404,-13.297 -7.404,-28.791 32.614,-28.791 ; 55.194,-28.791 55.194,-13.297 ; 87.376,-18.462 87.376,-13.297 ; 108.712,-18.462 108.712,-13.297 ; 124.511,-28.956 124.511,-23.804
  text "COMPONENTS MARKED 'DNP' SHOULD NOT BE POPULATED." at 29.299,-8.09 h1.52
  text "ASSEMBLY VARIANT:" at 29.286,-11.024 h1.52
  text ".VariantName" at 55.601,-11.024 h1.52
  text "PCB VIEWED FROM TOP SIDE" at -5.804,-16.654 h1.52
  text "BOARD #:" at 57.099,-16.654 h1.52
  text ".PRJ_Number" at 70.955,-16.654 h1.52
  text "REV:" at 92.405,-16.654 h1.52
  text ".PCB_Rev" at 99.809,-16.654 h1.52
  text "SVN REV:" at 113.69,-16.654 h1.52
  text ".VersionControl_RevNumber" at 126.543,-16.654 h1.52
  text "TID #:" at 57.099,-21.819 h1.52
  text ".TID" at 70.955,-21.819 h1.52
  text "PLOT NAME =" at -5.804,-27.034 h1.52
  text ".plot_File_Name" at 14.656,-27.034 h1.52
  text "GENERATED    :" at 57.15,-27.034 h1.52
  text ".Print_Date" at 79.235,-27.034 h1.52
  text ".Print_Time" at 97.752,-27.034 h1.52
  text "TEXAS INSTRUMENTS" at 129.87,-27.034 h1.52
M6 Assembly Bottom:
  lines w0.254: -7.429,-18.474 160.261,-18.474 ; -7.379,-23.639 160.261,-23.639 ; 28.334,-28.969 28.334,-23.817 ; 44.133,-18.474 44.133,-13.31 ; 65.468,-18.474 65.468,-13.31 ; 97.65,-28.804 97.65,-13.31 ; 120.231,-28.804 160.249,-28.804 160.249,-13.31 -7.429,-13.31 -7.429,-28.804 58.534,-28.804 160.261,-28.804 160.261,-13.31
  text "COMPONENTS MARKED 'DNP' SHOULD NOT BE POPULATED." at 154.991,-8.077 h1.52
  text ".VariantName" at 128.473,-11.024 h1.52
  text "ASSEMBLY VARIANT:" at 154.864,-11.024 h1.52
  text ".VersionControl_RevNumber" at 26.302,-16.667 h1.52
  text "SVN REV:" at 39.154,-16.667 h1.52
  text ".PCB_Rev" at 53.035,-16.667 h1.52
  text "REV:" at 60.439,-16.667 h1.52
  text ".PRJ_Number" at 81.89,-16.667 h1.52
  text "BOARD #:" at 95.745,-16.667 h1.52
  text "PCB VIEWED FROM BOTTOM SIDE" at 158.648,-16.667 h1.52
  text ".TID" at 81.89,-21.831 h1.52
  text "TID #:" at 95.745,-21.831 h1.52
  text "TEXAS INSTRUMENTS" at 22.974,-27.047 h1.52
  text ".Print_Time" at 55.093,-27.047 h1.52
  text ".Print_Date" at 73.609,-27.047 h1.52
  text "GENERATED    :" at 95.694,-27.047 h1.52
  text ".plot_File_Name" at 138.189,-27.047 h1.52
  text "PLOT NAME =" at 158.648,-27.047 h1.52
M9 Title Sheet:
  drawing of 57 lines, arcs and shapes, not listed
  text "1" at 18.792,204.127 h1.78
  text "2" at 82.182,204.127 h1.78
  text "3" at 145.411,204.127 h1.78
  text "4" at 209.08,204.127 h1.78
  text "5" at 272.555,204.127 h1.78
  text "6" at 336.182,204.127 h1.78
  text "A" at -10.579,175.095 h1.78
  text "A" at 365.341,175.095 h1.78
  text "B" at -10.579,114.643 h1.78
  text "B" at 365.341,114.643 h1.78
  text "C" at -10.579,54.318 h1.78
  text "C" at 365.341,54.318 h1.78
  text "PROJECT TITLE:" at 288.125,7.048 h1.14
  text ".PRJ_Title" at 289.395,3.662 h1.78
  text "DESIGNED FOR:" at 288.125,-0.597 h1.14
  text ".PRJ_Customer" at 289.395,-4.153 h1.78
  text "D" at -10.579,-5.88 h1.78
  text "D" at 365.341,-5.88 h1.78
  text "FILE NAME:" at 288.125,-8.217 h1.14
  text ".PCB_File_Name_No_Path" at 289.395,-11.265 h1.78
  text "Texas Instruments (TI) and/or its licensors do not warrant the accuracy or completeness of this specification" at 161.9,-15.376 h1.14
  text "ENGINEER:" at 288.125,-15.583 h1.14
  text "LAYOUT BY:" at 326.352,-15.583 h1.14
  text "or any information contained therein. TI and/or its licensors do not warrant that this design will meet" at 160.757,-18.237 h1.14
  text ".PRJ_Engineer" at 289.395,-19.52 h1.78
  text ".PCB_Layout" at 327.635,-19.52 h1.78
  text "the specifications, will be suitable for your application or fit for any particular purpose, or will operate in" at 160.757,-21.099 h1.14
  text ".Layer_Name" at 14.656,-21.806 h1.52
  text "ALTIUM DESIGNER VERSION:" at 326.352,-23.457 h1.14
  text "an implementation. TI and/or its licensors do not warrant that the design is production worthy. You should" at 160.757,-23.961 h1.14
  text "completely validate and test your design implementation to confirm the system functionality for your application." at 161.9,-26.822 h1.14
  text ".print_Scale" at 289.395,-26.843 h1.78
  text ".Application_BuildNumber" at 327.635,-26.843 h1.78
  text "1" at 18.792,-32.093 h1.78
  text "2" at 82.182,-32.093 h1.78
  text "3" at 145.411,-32.093 h1.78
  text "4" at 209.08,-32.093 h1.78
  text "5" at 272.555,-32.093 h1.78
  text "6" at 336.182,-32.093 h1.78
M10 Fab Notes:
  drawing of 173 lines, arcs and shapes, not listed
  text "DESIGN INFORMATION" at 314.402,157.505 h1.52
  text "MIN. TRACK WIDTH:" at 298.03,152.933 h1.52
  text "8" at 325.874,152.933 h1.52
  text "MIL" at 329.805,152.933 h1.52
  text "MIN. CLEARANCE:" at 298.03,149.581 h1.52
  text "0.2" at 324.35,149.581 h1.52
  text "mm" at 329.805,149.581 h1.52
  text "MIN. VIA PAD SIZE:" at 298.03,146.228 h1.52
  text "24" at 325.113,146.228 h1.52
  text "MIL" at 329.805,146.228 h1.52
  text "0.05mm (2MIL)" at 315.683,142.628 h1.52
  text "MINIMUM ANNULAR RING" at 289.667,142.52 h1.52
  text "EXTERNAL" at 333.666,142.52 h1.52
  text "PER" at 294.747,139.522 h1.52
  text "IPC-D-275 CLASS 2 LEVEL C" at 300.335,139.522 h1.52
  text "MIL, HOLES" at 338.136,136.67 h1.52
  text "+/-" at 328.168,136.652 h1.52
  text "+/-" at 349.86,136.652 h1.52
  text "REGISTRATION TOLERANCES:" at 289.667,136.525 h1.52
  text "METAL" at 320.142,136.525 h1.52
  text "5" at 334.777,136.525 h1.52
  text "3" at 355.935,136.525 h1.52
  text "MIL" at 358.888,136.525 h1.52
  text "+/-" at 349.86,133.655 h1.52
  text "HOLE SIZE TOLERANCE (UNLESS OTHERWISE SPECIFIED):" at 289.667,133.528 h1.52
  text "3" at 355.935,133.528 h1.52
  text "MIL" at 358.888,133.528 h1.52
  text "MATERIAL:" at 287.768,128.208 h1.52
  text "FR-4 High Tg" at 312.824,124.643 h1.52
  text "FR-408" at 298.462,124.425 h1.52
  text "OTHER" at 336.257,124.425 h1.52
  text "X" at 308.889,124.333 h1.52
  text "62 MIL (1.6mm) +/-10%" at 306.592,120.292 h1.52
  text "THICKNESS:" at 289.667,120.184 h1.52
  text "X" at 303.337,120.184 h1.52
  text "OTHER" at 339.229,120.184 h1.52
  text "TOLERANCE:" at 289.667,116.17 h1.52
  text "X" at 310.986,116.17 h1.52
  text "ANSI IPC-6012 TYPE 3 CLASS 2" at 315.734,116.17 h1.52
  text "OTHER +/-" at 315.734,112.208 h1.52
  text "BOW & TWIST:" at 289.667,108.22 h1.52
  text "X" at 310.986,108.22 h1.52
  text "ANSI IPC-6012 TYPE 3 CLASS 2" at 315.734,108.22 h1.52
  text "OTHER +/-" at 315.734,104.194 h1.52
  text "DRILLING:" at 287.768,100.676 h1.52
  text "REFERENCE:" at 289.667,97.705 h1.52
  text "X" at 306.132,97.705 h1.52
  text "AS SHOWN" at 310.882,97.705 h1.52
  text "X" at 329.018,97.705 h1.52
  text "NC_DRILL FILES" at 332.498,97.705 h1.52
  text "PTH COPPER THICKNESS:" at 289.667,93.691 h1.52
  text "X" at 318.375,93.691 h1.52
  text "20-30 um" at 321.855,93.691 h1.52
  text "OTHER" at 340.067,93.691 h1.52
  text "BOARD FINISH:" at 287.768,89.653 h1.52
  text "SILKSCREEN:" at 291.711,86.656 h1.52
  text "X" at 315.81,86.656 h1.52
  text "TOP" at 319.01,86.656 h1.52
  text "X" at 328.764,86.656 h1.52
  text "BOTTOM" at 331.99,86.656 h1.52
  text "SILKSCREEN COLOR:" at 291.711,82.414 h1.52
  text "X" at 315.783,82.414 h1.52
  text "WHITE" at 319.01,82.414 h1.52
  text "OTHER" at 331.99,82.414 h1.52
  text "X" at 319.111,78.37 h1.52
  text "GREEN" at 322.338,78.37 h1.52
  text "OTHER" at 338.035,78.37 h1.52
  text "SOLDER RESIST COLOR:" at 291.711,78.096 h1.52
  text "X" at 319.111,74.052 h1.52
  text "MATTE" at 322.338,74.052 h1.52
  text "SEMI-GLOSS" at 338.023,74.036 h1.52
  text "IMMERSION GOLD (ENIG)" at 314.718,69.264 h1.52
  text "ENEPIG" at 348.691,69.18 h1.52
  text "SURFACE FINISH:" at 287.768,69.155 h1.52
  text "X" at 309.969,69.155 h1.52
  text "IMM. TIN/SILVER OR EQUIV" at 296.139,65.167 h1.52
  text "OTHER" at 332.498,65.167 h1.52
  text "ARRAY/PANEL:" at 287.768,60.621 h1.52
  text "CUT AND TRIM PER M1 BOARD OUTLINE" at 314.718,60.512 h1.52
  text "N.C. ROUTE" at 314.718,56.658 h1.52
  text "X" at 331.964,56.658 h1.52
  text "V. SCORE" at 336.714,56.658 h1.52
  text "CERTIFICATION:" at 287.768,53.178 h1.52
  text "MATERIALS AND WORKMANSHIP FOR ALL PCBS" at 306.183,53.178 h1.52
  text "TO MEET OR EXCEED THE REQUIREMENTS OF:" at 306.183,50.689 h1.52
  text "X" at 296.696,47.222 h1.52
  text "ANSI IPC-A-600F CLASS ->" at 300.227,47.222 h1.52
  text "X" at 341.859,47.222 h1.52
  text "2" at 344.88,47.222 h1.52
  text "1" at 336.879,47.184 h1.52
  text "3" at 353.872,47.184 h1.52
  text "X" at 317.373,43.171 h1.52
  text "RoHS" at 320.852,43.171 h1.52
  text "OTHER" at 337.22,43.171 h1.52
  text "PER ORDER" at 347.305,43.171 h1.52
  text "ALL BOARDS MUST MEET OR EXCEED UL94-V0 REQUIREMENTS." at 288.468,38.964 h1.52
  text "PCB MUST BEAR THE UL94V-0 UL REGISTERED MATERIAL ID NUMBER" at 288.468,35.916 h1.52
  text "ADDITIONAL REQUIREMENTS:" at 287.768,31.512 h1.52
  text "MICROSECTION:" at 289.667,28.591 h1.52
  text "YES" at 312.673,28.591 h1.52
  text "REQUIRED" at 334.555,24.625 h1.52
  text "BARE BOARD ELEC. TEST:" at 289.667,24.553 h1.52
  text "NONE" at 322.833,24.553 h1.52
  text "X" at 331.329,24.553 h1.52
  text "PER ORDER" at 349.592,24.553 h1.52
  text ".Layer_Name" at 14.656,-21.806 h1.52
M11 Gerber Information:
  lines w0.254: -7.417,-23.626 160.223,-23.626 ; -7.417,-18.462 160.274,-18.462 ; -7.417,-13.297 -7.417,-28.791 94.31,-28.791 160.274,-28.791 160.274,-13.297 -7.404,-13.297 -7.404,-28.791 32.614,-28.791 ; 55.194,-28.791 55.194,-13.297 ; 87.376,-18.462 87.376,-13.297 ; 108.712,-18.462 108.712,-13.297 ; 124.511,-28.956 124.511,-23.804
  text "ALL ARTWORK VIEWED FROM TOP SIDE" at -5.804,-16.654 h1.52
  text "BOARD #:" at 57.099,-16.654 h1.52
  text ".PRJ_Number" at 70.955,-16.654 h1.52
  text "REV:" at 92.405,-16.654 h1.52
  text ".PCB_Rev" at 99.809,-16.654 h1.52
  text "SVN REV:" at 113.69,-16.654 h1.52
  text ".VersionControl_RevNumber" at 126.543,-16.654 h1.52
  text "LAYER NAME =" at -5.804,-21.806 h1.52
  text "TID #:" at 57.099,-21.819 h1.52
  text ".TID" at 70.955,-21.819 h1.52
  text "PLOT NAME =" at -5.804,-27.034 h1.52
  text ".plot_File_Name" at 14.656,-27.034 h1.52
  text "GENERATED    :" at 57.15,-27.034 h1.52
  text ".Print_Date" at 79.235,-27.034 h1.52
  text ".Print_Time" at 97.752,-27.034 h1.52
  text "TEXAS INSTRUMENTS" at 129.87,-27.034 h1.52
M12 Stackup:
  text ".Layer_Name" at 14.656,-21.806 h1.52
M13 Component Bodies Top:
  text ".Layer_Name" at 14.656,-21.806 h1.52
M14 Component Bodies Bottom:
  text ".Layer_Name" at 14.656,-21.806 h1.52
M15 Courtyards Top:
  text ".Layer_Name" at 14.656,-21.806 h1.52
M16 Courtyards Bottom:
  text ".Layer_Name" at 14.656,-21.806 h1.52
Drill Drawing:
  text ".Layer_Name" at 14.656,-21.806 h1.52
M17 Embedded Cavity:
  text ".Layer_Name" at 14.656,-21.806 h1.52
M18 Embedded Assembly:
  text ".Layer_Name" at 14.656,-21.806 h1.52
M19 Embedded Keepout:
  text ".Layer_Name" at 14.656,-21.806 h1.52

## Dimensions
0,-10.16 to 25.4,-10.16 on M2 Board Dimensions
